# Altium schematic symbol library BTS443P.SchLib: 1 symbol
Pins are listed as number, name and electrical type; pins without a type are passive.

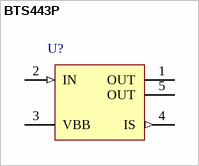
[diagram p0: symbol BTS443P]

## BTS443P
designator U?
Smart High-Side Power Switch, 1 Channel, 7.6 A Load Current, -40 to 150 degC, PG-TO252-5-11, Reel, Green; Manufacturer: Infineon; PartNumber: BTS443P; Channels: 1; Green: TRUE; Group: Automotive Qualified; Load Current (typ): 7.6 A; Ptot (max): 42 W; Recommended Operating Voltage Max.: 36 V; Recommended Operating Voltage Min.: 5 V; RON @ 25degreesC: 16 mOhm; RON(max) @ 150degreesC: 31 mOhm; toff (max): 410 us
footprint INF-PG-TO252-5-11_N (DPAK, 5-Leads, Body 6.5x6.12mm, Pitch 1.14mm, IPC Medium Density)
footprint INF-PG-TO252-5-11_L (DPAK, 5-Leads, Body 6.5x6.12mm, Pitch 1.14mm, IPC High Density)
footprint INF-PG-TO252-5-11_M (DPAK, 5-Leads, Body 6.5x6.12mm, Pitch 1.14mm, IPC Low Density)
pins: 1 OUT (power) "Output to the load. The pin 1 and 5 must be shorted with each other especially in high current applications!)", 2 IN (in) "Input, activates the power switch in case of short to ground", 3 VBB (power) "Positive power supply voltage, the tab is shorted to this pin.", 4 IS (out) "Diagnostic feedback providing a sense current proportional to the load current; high current on failure (see Truth Table on page 6)", 5 OUT (power) "Output to the load. The pin 1 and 5 must be shorted with each other especially in high current applications!)"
